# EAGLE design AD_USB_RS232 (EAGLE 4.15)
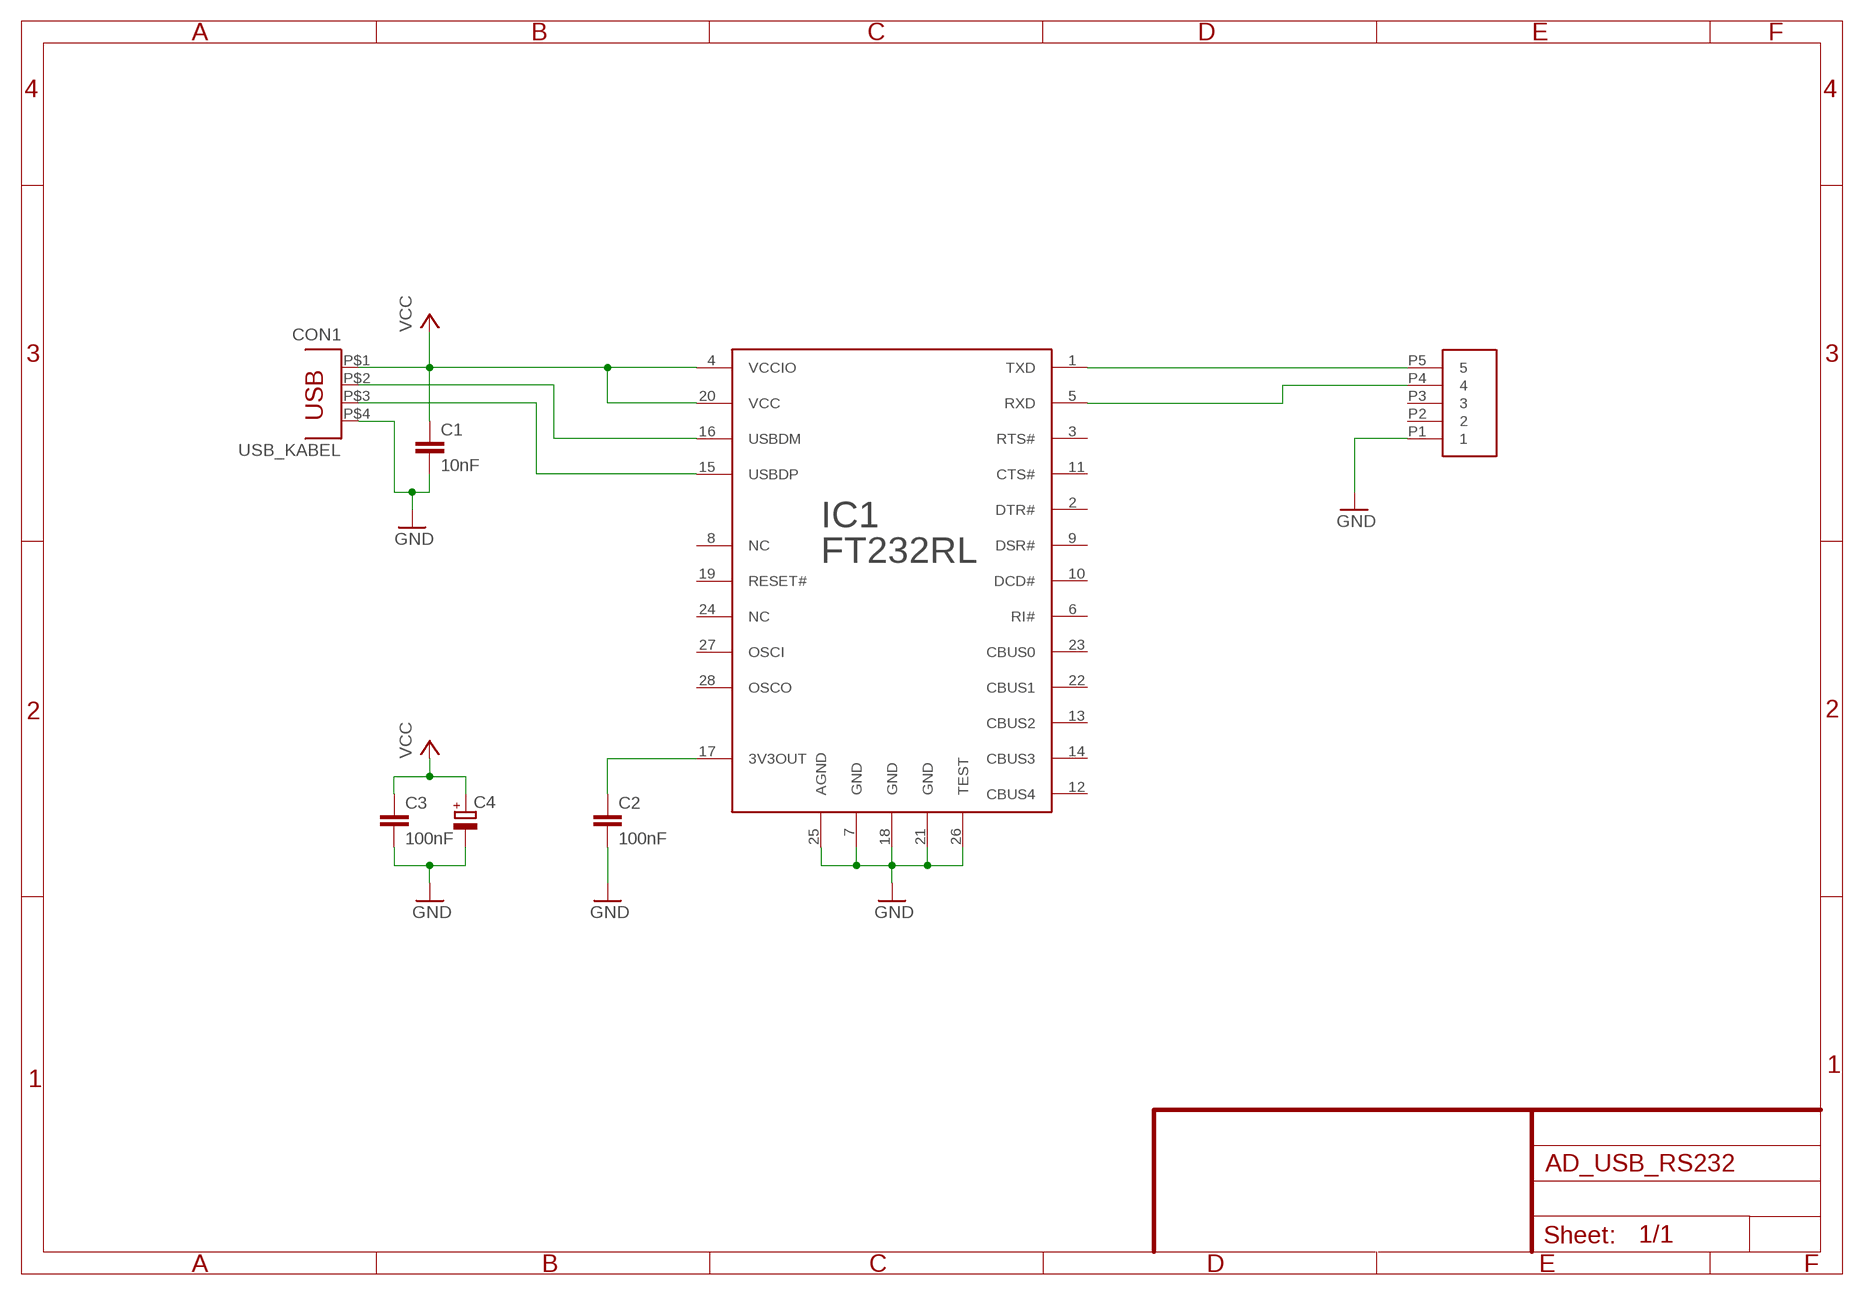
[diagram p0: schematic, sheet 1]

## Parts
C1  10nF  C-EUC0805  [C0805]
C2  100nF  C-EUC0805  [C0805]
C3  100nF  C-EUC0805  [C0805]
C4  CPOL-EU085CS-1AR  [085CS_1AR]
CON1  USB_KABEL  [USB_CABEL_DIREKT]
CON2  RS_CON_F  [F80-614-5]
IC1  FT232RL  [SSOP28]

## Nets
GND: C1.2 C2.2 C3.2 C4.- CON1.P$4 CON2.P1 IC1.7(GND) IC1.18(GND) IC1.21(GND) IC1.25(AGND) IC1.26(TEST)
N$1: CON1.P$2 IC1.16(USBDM)
N$2: CON1.P$3 IC1.15(USBDP)
N$4: CON2.P5 IC1.1(TXD)
N$5: C2.1 IC1.17(3V3OUT)
N$6: CON2.P4 IC1.5(RXD)
VCC: C1.1 C3.1 C4.+ CON1.P$1 IC1.4(VCCIO) IC1.20(VCC)
Unconnected: CON2.P2 CON2.P3 IC1.2(DTR#) IC1.3(RTS#) IC1.6(RI#) IC1.8(NC) IC1.9(DSR#) IC1.10(DCD#) IC1.11(CTS#) IC1.12(CBUS4) IC1.13(CBUS2) IC1.14(CBUS3) IC1.19(RESET#) IC1.22(CBUS1) IC1.23(CBUS0) IC1.24(NC) IC1.27(OSCI) IC1.28(OSCO)

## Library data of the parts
C1-C3 = rcl:C-EU: CAPACITOR, European symbol
C4 = rcl:CPOL-EU: POLARIZED CAPACITOR, European symbol
CON1 = FTDI:USB_KABEL
CON2 = FTDI:RS_CON_F
IC1 = FTDI:FT232RL

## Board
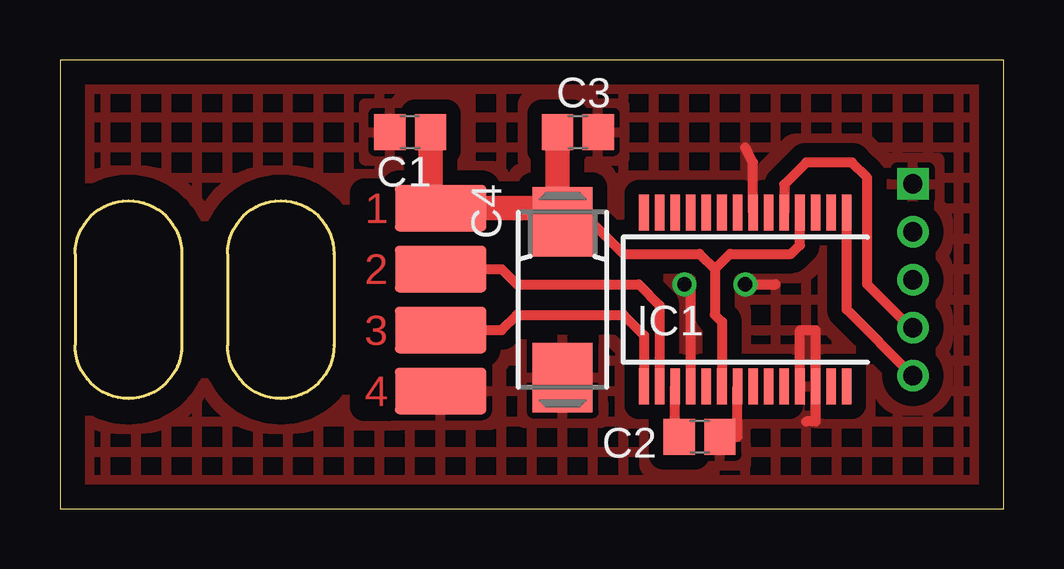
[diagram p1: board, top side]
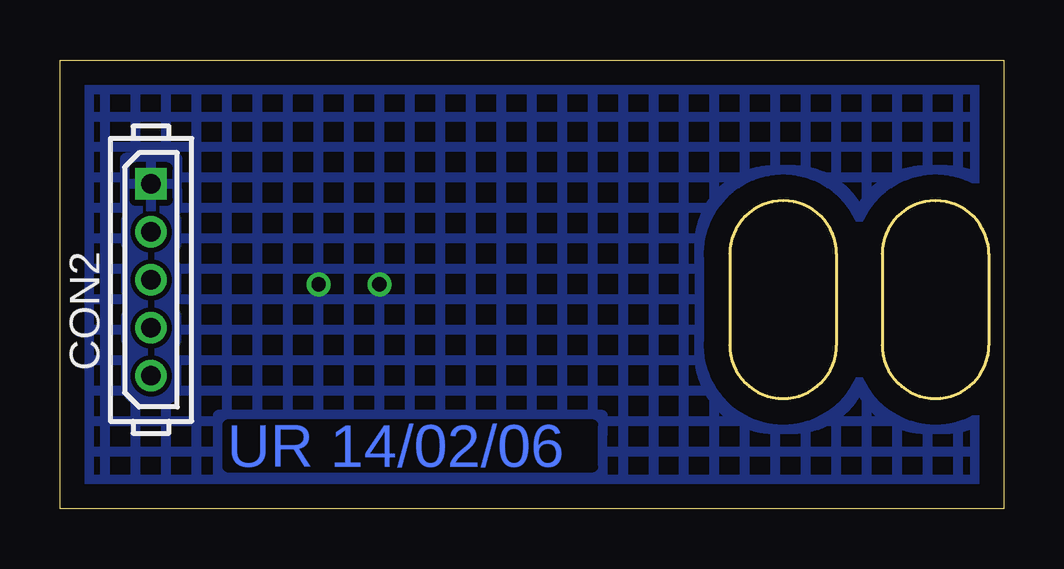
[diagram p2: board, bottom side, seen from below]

Size 39.35 x 18.72 mm. Coordinates in mm from the lower left corner, seen from the top.
Outline: 0,0 39.35,0 39.35,18.72 0,18.72 0,0
Copper layers (1*16): Top 0.035mm / dielectric 1.5mm / Bottom 0.035mm
Design rules "default": minimum track width 10mil, minimum drill 24mil, track to track 8mil, track to pad 8mil, pad to pad 8mil, via to via 8mil, smd to smd 8mil, copper to edge 40mil, drill to drill 8mil, minimum pad ring 10mil, minimum via ring 8mil, stop-mask expansion 4mil, vias tented up to drill 0mil, thermal gap 10mil

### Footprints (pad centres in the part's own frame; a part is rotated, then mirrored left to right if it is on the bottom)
C0805 = smd 1.3 x 1.5: 1 -0.85,0; 2 0.85,0
085CS_1AR = smd 2.9 x 2.5: + 3.25,0; - -3.25,0
USB_CABEL_DIREKT = smd 3.81 x 1.93: P$1 2.54,3.81; P$2 2.54,1.27; P$3 2.54,-1.27; P$4 2.54,-3.81
F80-614-5 = drill 0.8 square: P1 8,0 | drill 0.8 round: P2 6,0; P3 4,0; P4 2,0; P5 0,0
SSOP28 = smd 0.4 x 1.5: 1 -4.225,-3.625; 2 -3.575,-3.625; 3 -2.925,-3.625; 4 -2.275,-3.625; 5 -1.625,-3.625; 6 -0.975,-3.625; 7 -0.325,-3.625; 8 0.325,-3.625; 9 0.975,-3.625; 10 1.625,-3.625; 11 2.275,-3.625; 12 2.925,-3.625; 13 3.575,-3.625; 14 4.225,-3.625; 15 4.225,3.625; 16 3.575,3.625; 17 2.925,3.625; 18 2.275,3.625; 19 1.625,3.625; 20 0.975,3.625; 21 0.325,3.625; 22 -0.325,3.625; 23 -0.975,3.625; 24 -1.625,3.625; 25 -2.275,3.625; 26 -2.925,3.625; 27 -3.575,3.625; 28 -4.225,3.625

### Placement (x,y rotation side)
C1  14.6,15.71 180 top
C2  26.66,3.01 0 top
C3  21.58,15.71 0 top
C4  20.95,8.72 90 top
CON1  13.33,8.72 0 top
CON2  35.55,5.55 90 bottom
IC1  28.57,8.72 180 top

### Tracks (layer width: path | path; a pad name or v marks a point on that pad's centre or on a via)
GND  (via drill 0.6)
  Top 0.406: IC1.7 28.89,14.44 28.57,15.08 | 31.11,3.65 31.49,3.65 IC1.26 31.49,7.46 30.84,7.46 IC1.25 | IC1.21 28.24,3.01 27.93,3.01 | IC1.18 26.29,9.09 v26.03,9.36 | v28.57,9.36 29.84,9.36
  pour Top (isolate 0.61, hatched): 0.63,18.25 0.63,0.47 38.73,0.47 38.73,18.25
  pour Bottom (hatched): 0.63,18.25 38.73,18.25 38.73,0.47 0.63,0.47
N$1
  Top 0.406: CON1.P$2 18.41,9.99 19.04,9.36 24.12,9.36 24.99,8.49 IC1.16
N$2
  Top 0.406: IC1.15 24.34,7.23 23.49,8.09 19.04,8.09 18.41,7.46 CON1.P$3
N$4
  Top 0.406: IC1.1 32.8,8.31 CON2.P5
N$5
  Top 0.406: 26.03,3.01 C2.1 25.64,3.01 IC1.17
N$6
  Top 0.406: IC1.5 30.2,13.53 31.11,14.44 33.02,14.44 33.65,13.8 33.65,9.36 35.55,7.46 CON2.P4
VCC
  Top 0.406: 20.95,12.54 C4.+ 22.14,11.97 23.49,10.63 26.66,10.63 27.3,9.99 | 27.3,9.99 27.93,10.63 30.47,10.63 30.84,11 IC1.4 | 27.3,9.99 27.3,8.09 27.59,7.79 IC1.20
  Top 1.016: C3.1 20.73,12.75 20.95,12.54 CON1.P$1 15.45,12.96 C1.1

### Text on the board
Bottom: UR 14/02/06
